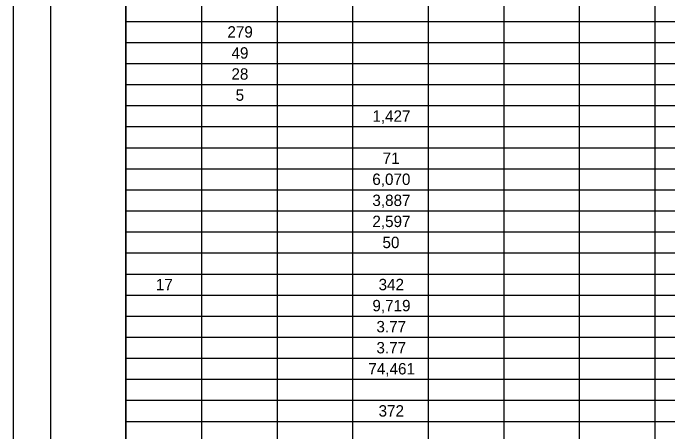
# Model space of a CAD drawing. Extents: x 0 to 34, y 0 to 22.
# Drawn here: x 0 to 8.71, y 11 to 16.57 of the extents above; entities that cross this region are included whole.
import ezdxf

# ---------------------------------------------------------------- set-up
doc = ezdxf.new("R2010")
doc.units = 0
for name, color, linetype in [('GM_X_County', 7, 'Continuous'), ('GM_X_Minor_Lake', 7, 'Continuous'), ('GM_X_Minor_River_Text', 7, 'Continuous')]:
    doc.layers.add(name, color=color, linetype=linetype)

msp = doc.modelspace()

# ---------------------------------------------------------------- linework, layer by layer
at = {"layer": 'GM_X_County'}
msp.add_lwpolyline([(0, 0), (34, 0), (34, 22), (0, 22)], close=True, dxfattribs=at)
at = {"layer": 'GM_X_Minor_Lake'}
for p, q in [((1.5, 21.5), (1.5, 0.5)), ((2.5046, 20.94), (2.5046, 0.5)), ((3.5092, 20.94), (3.5092, 0.5)), ((4.5138, 20.94), (4.5138, 0.5)), ((5.5184, 20.94), (5.5184, 0.5)), ((6.5229, 20.94), (6.5229, 0.5)), ((7.5275, 20.94), (7.5275, 0.5)), ((8.5321, 20.94), (8.5321, 0.5)), ((1.5, 16.46), (32, 16.46)), ((1.5, 16.18), (32, 16.18)), ((1.5, 15.9), (32, 15.9)), ((1.5, 15.62), (32, 15.62)), ((1.5, 15.34), (32, 15.34)), ((1.5, 15.06), (32, 15.06)), ((1.5, 14.78), (32, 14.78)), ((1.5, 14.5), (32, 14.5)), ((1.5, 14.22), (32, 14.22)), ((1.5, 13.94), (32, 13.94)), ((1.5, 13.66), (32, 13.66)), ((1.5, 13.38), (32, 13.38)), ((1.5, 13.1), (32, 13.1)), ((1.5, 12.82), (32, 12.82)), ((1.5, 12.54), (32, 12.54)), ((1.5, 12.26), (32, 12.26)), ((1.5, 11.98), (32, 11.98)), ((1.5, 11.7), (32, 11.7)), ((1.5, 11.42), (32, 11.42)), ((1.5, 11.14), (32, 11.14))]:
    msp.add_line(p, q, dxfattribs=at)
at = {"layer": 'GM_X_Minor_River_Text'}
for points in [[(0.5, 21.5), (1.5, 21.5), (1.5, 0.5), (0.5, 0.5)], [(1.5, 21.5), (33.5, 21.5), (33.5, 0.5), (1.5, 0.5)]]:
    msp.add_lwpolyline(points, close=True, dxfattribs=at)

# ---------------------------------------------------------------- texts
at = {"layer": 'GM_X_Minor_Lake'}
for s, height, p in [('279', 0.15153, (2.8491, 16.2442)), ('49', 0.15153, (2.9035, 15.9642)), ('28', 0.15153, (2.9025, 15.6842)), ('5', 0.1515, (2.9587, 15.4042)), ('1,427', 0.15153, (4.7765, 15.1242)), ('71', 0.15153, (4.9131, 14.5642)), ('6,070', 0.15153, (4.7753, 14.2842)), ('3,887', 0.15153, (4.7765, 14.0042)), ('2,597', 0.15153, (4.7765, 13.7242)), ('50', 0.15153, (4.9109, 13.4442)), ('17', 0.15153, (1.8984, 12.8842)), ('342', 0.15153, (4.8588, 12.8842)), ('9,719', 0.15153, (4.777, 12.6042)), ('3.77', 0.15153, (4.8306, 12.3242)), ('3.77', 0.15153, (4.8306, 12.0442)), ('74,461', 0.15153, (4.723, 11.7642)), ('372', 0.15153, (4.8588, 11.2042))]:
    msp.add_text(s, height=height, dxfattribs=at).set_placement(p)

doc.saveas('drawing.dxf')
